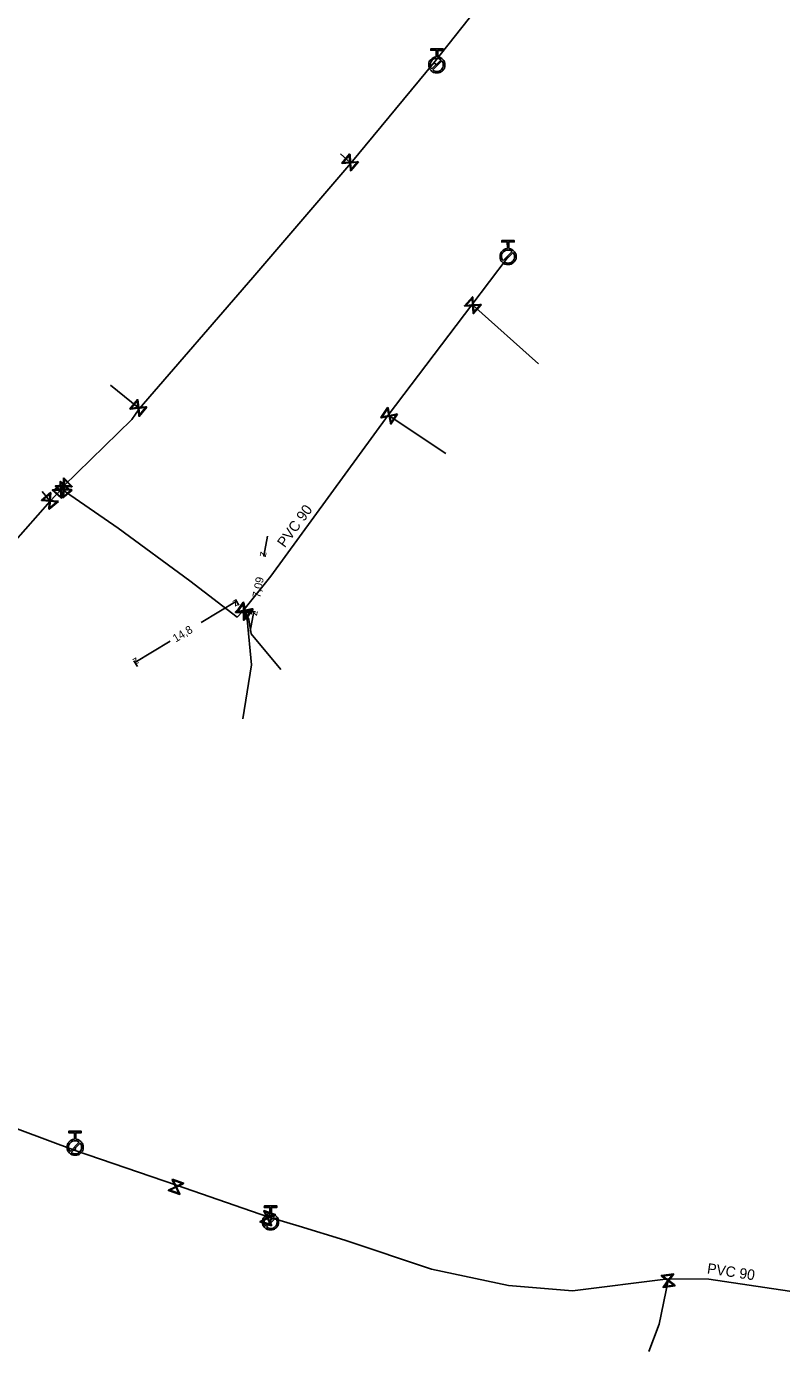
# Model space of a CAD drawing. Extents: x -641905 to -641246, y -1111750 to -1110210.
# Drawn here: x -641611.1 to -641516.8, y -1110757.5 to -1110592 of the extents above; entities that cross this region are included whole.
import ezdxf

# ---------------------------------------------------------------- set-up
doc = ezdxf.new("R2010")
doc.units = 0
for name, color, linetype in [('Default', 7, 'Continuous'), ('VP Hydrant', 7, 'Continuous'), ('VP Kótování', 7, 'Continuous'), ('VP Přípojka', 7, 'Continuous'), ('VP Řad', 7, 'Continuous'), ('VP Řad - popis', 7, 'Continuous'), ('VP Šoupě', 7, 'Continuous')]:
    doc.layers.add(name, color=color, linetype=linetype)

msp = doc.modelspace()

# ---------------------------------------------------------------- linework, layer by layer
at = {"layer": 'Default'}
for points in [[(-641559.74, -1110595.79), (-641559.39, -1110595.82), (-641559.13, -1110596.08), (-641558.84, -1110596.38), (-641558.85, -1110596.8), (-641558.86, -1110597.21), (-641559.15, -1110597.5), (-641559.45, -1110597.79), (-641559.87, -1110597.78), (-641560.28, -1110597.77), (-641560.57, -1110597.48), (-641560.86, -1110597.18), (-641560.85, -1110596.77), (-641560.84, -1110596.35), (-641560.55, -1110596.06), (-641560.29, -1110595.81), (-641559.93, -1110595.78)], [(-641559.33, -1110596.15), (-641559.55, -1110595.97), (-641559.84, -1110595.97), (-641560.18, -1110595.96), (-641560.42, -1110596.19), (-641560.66, -1110596.43), (-641560.66, -1110596.77), (-641560.67, -1110597.06), (-641560.49, -1110597.28)], [(-641560.37, -1110597.41), (-641560.15, -1110597.59), (-641559.86, -1110597.59), (-641559.53, -1110597.6), (-641559.29, -1110597.36), (-641559.04, -1110597.13), (-641559.04, -1110596.79), (-641559.04, -1110596.5), (-641559.21, -1110596.28)], [(-641550.86, -1110619.72), (-641550.5, -1110619.75), (-641550.24, -1110620.01), (-641549.95, -1110620.3), (-641549.95, -1110620.72), (-641549.95, -1110621.13), (-641550.24, -1110621.43), (-641550.53, -1110621.72), (-641550.95, -1110621.72), (-641551.36, -1110621.72), (-641551.65, -1110621.43), (-641551.95, -1110621.14), (-641551.95, -1110620.73), (-641551.95, -1110620.31), (-641551.66, -1110620.02), (-641551.4, -1110619.75), (-641551.04, -1110619.72)], [(-641550.44, -1110620.08), (-641550.66, -1110619.9), (-641550.95, -1110619.91), (-641551.29, -1110619.91), (-641551.53, -1110620.15), (-641551.77, -1110620.38), (-641551.76, -1110620.72), (-641551.76, -1110621.01), (-641551.58, -1110621.23)], [(-641551.45, -1110621.36), (-641551.24, -1110621.53), (-641550.95, -1110621.53), (-641550.61, -1110621.53), (-641550.38, -1110621.29), (-641550.14, -1110621.05), (-641550.14, -1110620.72), (-641550.14, -1110620.43), (-641550.31, -1110620.21)], [(-641604.96, -1110731), (-641604.6, -1110731.03), (-641604.34, -1110731.29), (-641604.05, -1110731.58), (-641604.05, -1110732), (-641604.05, -1110732.41), (-641604.34, -1110732.7), (-641604.63, -1110733), (-641605.05, -1110733), (-641605.46, -1110733), (-641605.75, -1110732.71), (-641606.05, -1110732.42), (-641606.05, -1110732.01), (-641606.05, -1110731.59), (-641605.76, -1110731.3), (-641605.51, -1110731.03), (-641605.15, -1110731)], [(-641604.55, -1110731.36), (-641604.76, -1110731.18), (-641605.06, -1110731.19), (-641605.39, -1110731.19), (-641605.63, -1110731.43), (-641605.87, -1110731.66), (-641605.86, -1110732), (-641605.86, -1110732.29), (-641605.68, -1110732.51)], [(-641605.55, -1110732.64), (-641605.34, -1110732.81), (-641605.05, -1110732.81), (-641604.71, -1110732.81), (-641604.48, -1110732.57), (-641604.24, -1110732.33), (-641604.24, -1110731.99), (-641604.24, -1110731.71), (-641604.42, -1110731.49)], [(-641580.53, -1110740.33), (-641580.18, -1110740.36), (-641579.92, -1110740.63), (-641579.63, -1110740.92), (-641579.63, -1110741.34), (-641579.63, -1110741.75), (-641579.93, -1110742.04), (-641580.22, -1110742.33), (-641580.64, -1110742.33), (-641581.05, -1110742.33), (-641581.34, -1110742.04), (-641581.63, -1110741.74), (-641581.63, -1110741.33), (-641581.63, -1110740.91), (-641581.34, -1110740.62), (-641581.08, -1110740.36), (-641580.72, -1110740.33)], [(-641580.12, -1110740.69), (-641580.34, -1110740.52), (-641580.63, -1110740.52), (-641580.97, -1110740.51), (-641581.21, -1110740.75), (-641581.44, -1110740.99), (-641581.44, -1110741.33), (-641581.45, -1110741.62), (-641581.27, -1110741.84)], [(-641581.14, -1110741.96), (-641580.92, -1110742.14), (-641580.63, -1110742.14), (-641580.3, -1110742.14), (-641580.06, -1110741.91), (-641579.82, -1110741.67), (-641579.82, -1110741.33), (-641579.82, -1110741.04), (-641579.99, -1110740.82)]]:
    msp.add_open_spline(points, degree=3, dxfattribs=at)
at = {"layer": 'VP Hydrant'}
for points in [[(-641559.93, -1110595.78), (-641559.92, -1110594.96), (-641560.61, -1110594.95), (-641560.6, -1110594.77), (-641559.04, -1110594.79), (-641559.04, -1110594.97), (-641559.73, -1110594.97), (-641559.74, -1110595.79)], [(-641560.49, -1110597.28), (-641559.33, -1110596.15)], [(-641559.21, -1110596.28), (-641560.37, -1110597.41)], [(-641551.04, -1110619.72), (-641551.05, -1110618.9), (-641551.74, -1110618.91), (-641551.74, -1110618.72), (-641550.18, -1110618.72), (-641550.17, -1110618.9), (-641550.86, -1110618.9), (-641550.86, -1110619.72)], [(-641551.58, -1110621.23), (-641550.44, -1110620.08)], [(-641550.31, -1110620.21), (-641551.45, -1110621.36)], [(-641605.15, -1110731), (-641605.15, -1110730.18), (-641605.84, -1110730.19), (-641605.84, -1110730), (-641604.28, -1110730), (-641604.28, -1110730.18), (-641604.97, -1110730.18), (-641604.96, -1110731)], [(-641605.68, -1110732.51), (-641604.55, -1110731.36)], [(-641604.42, -1110731.49), (-641605.55, -1110732.64)], [(-641580.72, -1110740.33), (-641580.72, -1110739.51), (-641581.41, -1110739.51), (-641581.4, -1110739.33), (-641579.84, -1110739.33), (-641579.84, -1110739.52), (-641580.53, -1110739.51), (-641580.53, -1110740.33)], [(-641581.27, -1110741.84), (-641580.12, -1110740.69)], [(-641579.99, -1110740.82), (-641581.14, -1110741.96)]]:
    msp.add_lwpolyline(points, dxfattribs=at)
at = {"layer": 'VP Kótování'}
for points in [[(-641581.02, -1110655.65), (-641581.47, -1110658.11)], [(-641581.52, -1110658.1), (-641581.22, -1110658.15)], [(-641589.31, -1110666.45), (-641584.9, -1110663.79)], [(-641584.6, -1110664.29), (-641585.03, -1110663.58)], [(-641583.19, -1110667.54), (-641582.74, -1110665.08)], [(-641582.79, -1110665.07), (-641582.5, -1110665.12)], [(-641593.16, -1110668.78), (-641597.57, -1110671.44)], [(-641597.27, -1110671.94), (-641597.7, -1110671.23)]]:
    msp.add_lwpolyline(points, dxfattribs=at)
at = {"layer": 'VP Přípojka'}
for points in [[(-641560.21, -1110596.51), (-641560.03, -1110596.65), (-641559.85, -1110596.78)], [(-641570.58, -1110609.06), (-641570.68, -1110608.97), (-641571.9, -1110607.91)], [(-641551.08, -1110620.91), (-641550.95, -1110620.72)], [(-641555.46, -1110626.76), (-641555.34, -1110626.81), (-641547.13, -1110634.11)], [(-641597.05, -1110639.76), (-641597.15, -1110639.63), (-641600.65, -1110636.79)], [(-641565.92, -1110640.54), (-641565.79, -1110640.62), (-641558.72, -1110645.33)], [(-641608.2, -1110651.25), (-641609.19, -1110650.09)], [(-641584.1, -1110678.47), (-641583.02, -1110671.73), (-641583.57, -1110666.06), (-641583.97, -1110665.12), (-641584.08, -1110665.01)], [(-641583.95, -1110664.87), (-641583.85, -1110664.94), (-641583.36, -1110666.08), (-641583.07, -1110667.84)], [(-641583.07, -1110667.84), (-641579.33, -1110672.31)], [(-641605.04, -1110732.39), (-641604.99, -1110732.24), (-641605.05, -1110732)], [(-641592.38, -1110736.75), (-641592.44, -1110736.94)], [(-641580.95, -1110740.68), (-641581, -1110740.85)], [(-641580.55, -1110740.8), (-641580.6, -1110741.04), (-641580.63, -1110741.33)], [(-641530.96, -1110748.44), (-641530.93, -1110748.65), (-641532.07, -1110754.09), (-641533.35, -1110757.51)]]:
    msp.add_lwpolyline(points, dxfattribs=at)
at = {"layer": 'VP Řad'}
for points in [[(-641606.72, -1110649.72), (-641606.63, -1110649.64), (-641606.61, -1110649.53), (-641606.49, -1110649.41), (-641597.96, -1110641.06), (-641597.05, -1110639.76), (-641582.85, -1110623.35), (-641570.58, -1110609.06), (-641560.21, -1110596.51), (-641554.97, -1110589.92), (-641538.7, -1110571.11), (-641533.56, -1110565.36), (-641525.73, -1110556.61), (-641525.22, -1110556.04), (-641523.66, -1110554.29), (-641522.92, -1110554.82), (-641518.3, -1110558.16), (-641514.31, -1110561.04), (-641510.94, -1110563.03), (-641509.87, -1110563.7)], [(-641606.63, -1110649.64), (-641606.6, -1110649.69), (-641606.49, -1110649.81), (-641606.24, -1110650.1), (-641599.67, -1110654.67), (-641590.73, -1110661.24), (-641584.82, -1110665.77), (-641584.08, -1110665.01), (-641583.95, -1110664.87), (-641580.61, -1110660.63), (-641565.92, -1110640.54), (-641555.46, -1110626.76), (-641551.08, -1110620.91)], [(-641643.86, -1110695.96), (-641643.82, -1110695.92), (-641643.71, -1110695.79), (-641639.46, -1110690.99), (-641631.18, -1110680.23), (-641624.38, -1110671.68), (-641621.52, -1110667.9), (-641614.34, -1110658.28), (-641608.15, -1110651.29), (-641606.84, -1110649.85), (-641606.72, -1110649.72)], [(-641624.02, -1110725.37), (-641622.04, -1110726.09), (-641605.04, -1110732.39), (-641592.38, -1110736.75), (-641580.95, -1110740.68), (-641580.55, -1110740.8), (-641577.05, -1110741.87), (-641571.34, -1110743.62), (-641560.51, -1110747.22), (-641550.89, -1110749.28), (-641542.88, -1110749.95), (-641530.96, -1110748.44), (-641525.88, -1110748.46), (-641513.84, -1110750.25), (-641507.42, -1110753.04), (-641507.31, -1110753.07)]]:
    msp.add_lwpolyline(points, dxfattribs=at)
at = {"layer": 'VP Šoupě'}
for points in [[(-641569.62, -1110608.9), (-641570.61, -1110610.03), (-641570.66, -1110609.99), (-641570.66, -1110609.86), (-641570.72, -1110609.02), (-641571.69, -1110609.09), (-641571.74, -1110609.04), (-641570.75, -1110607.91), (-641570.7, -1110607.96), (-641570.64, -1110608.92), (-641569.8, -1110608.87), (-641569.67, -1110608.85), (-641569.62, -1110608.9)], [(-641571.57, -1110608.99), (-641570.73, -1110608.93), (-641570.79, -1110608.09), (-641571.57, -1110608.99)], [(-641569.8, -1110608.95), (-641570.63, -1110609.01), (-641570.57, -1110609.85), (-641569.8, -1110608.95)], [(-641554.28, -1110626.75), (-641555.28, -1110627.87), (-641555.33, -1110627.83), (-641555.33, -1110627.7), (-641555.38, -1110626.86), (-641556.35, -1110626.92), (-641556.4, -1110626.87), (-641555.4, -1110625.75), (-641555.35, -1110625.8), (-641555.3, -1110626.77), (-641554.46, -1110626.71), (-641554.33, -1110626.7), (-641554.28, -1110626.75)], [(-641556.23, -1110626.82), (-641555.39, -1110626.77), (-641555.44, -1110625.93), (-641556.23, -1110626.82)], [(-641554.46, -1110626.8), (-641555.29, -1110626.85), (-641555.24, -1110627.69), (-641554.46, -1110626.8)], [(-641596.09, -1110639.52), (-641597.04, -1110640.69), (-641597.09, -1110640.64), (-641597.1, -1110640.52), (-641597.19, -1110639.68), (-641598.15, -1110639.78), (-641598.2, -1110639.74), (-641597.26, -1110638.58), (-641597.21, -1110638.62), (-641597.11, -1110639.58), (-641596.27, -1110639.5), (-641596.15, -1110639.48), (-641596.09, -1110639.52)], [(-641598.04, -1110639.68), (-641597.2, -1110639.59), (-641597.29, -1110638.76), (-641598.04, -1110639.68)], [(-641596.27, -1110639.58), (-641597.1, -1110639.67), (-641597.01, -1110640.5), (-641596.27, -1110639.58)], [(-641564.75, -1110640.41), (-641565.58, -1110641.66), (-641565.64, -1110641.62), (-641565.66, -1110641.5), (-641565.82, -1110640.67), (-641566.78, -1110640.87), (-641566.83, -1110640.83), (-641566, -1110639.58), (-641565.94, -1110639.62), (-641565.75, -1110640.57), (-641564.93, -1110640.4), (-641564.8, -1110640.38), (-641564.75, -1110640.41)], [(-641566.67, -1110640.75), (-641565.84, -1110640.59), (-641566.01, -1110639.76), (-641566.67, -1110640.75)], [(-641564.92, -1110640.49), (-641565.74, -1110640.66), (-641565.57, -1110641.48), (-641564.92, -1110640.49)], [(-641606.89, -1110648.79), (-641605.78, -1110649.8), (-641605.83, -1110649.85), (-641605.95, -1110649.85), (-641606.79, -1110649.89), (-641606.75, -1110650.86), (-641606.79, -1110650.91), (-641607.9, -1110649.9), (-641607.86, -1110649.85), (-641606.89, -1110649.81), (-641606.93, -1110648.97), (-641606.93, -1110648.84), (-641606.89, -1110648.79)], [(-641605.44, -1110649.89), (-641606.57, -1110650.87), (-641606.61, -1110650.83), (-641606.6, -1110650.7), (-641606.55, -1110649.86), (-641607.52, -1110649.8), (-641607.56, -1110649.75), (-641606.43, -1110648.76), (-641606.39, -1110648.81), (-641606.45, -1110649.78), (-641605.62, -1110649.83), (-641605.49, -1110649.84), (-641605.44, -1110649.89)], [(-641606.47, -1110648.36), (-641605.42, -1110649.43), (-641605.47, -1110649.48), (-641605.6, -1110649.47), (-641606.44, -1110649.46), (-641606.45, -1110650.43), (-641606.49, -1110650.48), (-641607.54, -1110649.41), (-641607.5, -1110649.36), (-641606.53, -1110649.37), (-641606.52, -1110648.53), (-641606.52, -1110648.4), (-641606.47, -1110648.36)], [(-641607.38, -1110649.72), (-641606.54, -1110649.77), (-641606.49, -1110648.93), (-641607.38, -1110649.72)], [(-641606.84, -1110648.97), (-641606.8, -1110649.8), (-641605.96, -1110649.76), (-641606.84, -1110648.97)], [(-641606.43, -1110648.54), (-641606.44, -1110649.37), (-641605.6, -1110649.38), (-641606.43, -1110648.54)], [(-641607.15, -1110651.32), (-641608.29, -1110652.3), (-641608.34, -1110652.25), (-641608.32, -1110652.12), (-641608.26, -1110651.28), (-641609.22, -1110651.21), (-641609.27, -1110651.16), (-641608.13, -1110650.18), (-641608.09, -1110650.23), (-641608.16, -1110651.2), (-641607.32, -1110651.27), (-641607.2, -1110651.27), (-641607.15, -1110651.32)], [(-641609.09, -1110651.13), (-641608.25, -1110651.19), (-641608.19, -1110650.36), (-641609.09, -1110651.13)], [(-641606.84, -1110650.74), (-641606.88, -1110649.9), (-641607.72, -1110649.94), (-641606.84, -1110650.74)], [(-641606.53, -1110650.3), (-641606.53, -1110649.46), (-641607.37, -1110649.45), (-641606.53, -1110650.3)], [(-641605.62, -1110649.92), (-641606.46, -1110649.86), (-641606.51, -1110650.7), (-641605.62, -1110649.92)], [(-641607.33, -1110651.35), (-641608.17, -1110651.29), (-641608.23, -1110652.12), (-641607.33, -1110651.35)], [(-641582.82, -1110664.76), (-641583.68, -1110665.99), (-641583.73, -1110665.95), (-641583.75, -1110665.83), (-641583.9, -1110665), (-641584.85, -1110665.17), (-641584.91, -1110665.13), (-641584.05, -1110663.9), (-641583.99, -1110663.94), (-641583.82, -1110664.9), (-641583, -1110664.75), (-641582.87, -1110664.73), (-641582.82, -1110664.76)], [(-641582.91, -1110665.12), (-641583.97, -1110666.18), (-641584.02, -1110666.14), (-641584.02, -1110666.01), (-641584.02, -1110665.17), (-641584.99, -1110665.17), (-641585.03, -1110665.12), (-641583.97, -1110664.06), (-641583.93, -1110664.11), (-641583.93, -1110665.08), (-641583.09, -1110665.08), (-641582.96, -1110665.07), (-641582.91, -1110665.12)], [(-641584.86, -1110665.08), (-641584.02, -1110665.08), (-641584.02, -1110664.24), (-641584.86, -1110665.08)], [(-641584.74, -1110665.06), (-641583.91, -1110664.91), (-641584.06, -1110664.08), (-641584.74, -1110665.06)], [(-641583.09, -1110665.17), (-641583.93, -1110665.17), (-641583.93, -1110666), (-641583.09, -1110665.17)], [(-641582.98, -1110664.84), (-641583.81, -1110664.98), (-641583.66, -1110665.81), (-641582.98, -1110664.84)], [(-641592.9, -1110735.98), (-641591.49, -1110736.47), (-641591.51, -1110736.53), (-641591.63, -1110736.59), (-641592.38, -1110736.96), (-641591.95, -1110737.83), (-641591.97, -1110737.89), (-641593.39, -1110737.4), (-641593.37, -1110737.34), (-641592.5, -1110736.92), (-641592.87, -1110736.16), (-641592.93, -1110736.05), (-641592.9, -1110735.98)], [(-641592.79, -1110736.12), (-641592.42, -1110736.88), (-641591.67, -1110736.51), (-641592.79, -1110736.12)], [(-641592.09, -1110737.75), (-641592.46, -1110736.99), (-641593.21, -1110737.36), (-641592.09, -1110737.75)], [(-641581.47, -1110739.9), (-641580.05, -1110740.38), (-641580.07, -1110740.45), (-641580.19, -1110740.5), (-641580.94, -1110740.87), (-641580.51, -1110741.74), (-641580.53, -1110741.8), (-641581.95, -1110741.32), (-641581.93, -1110741.25), (-641581.06, -1110740.83), (-641581.43, -1110740.07), (-641581.49, -1110739.96), (-641581.47, -1110739.9)], [(-641581.35, -1110740.04), (-641580.98, -1110740.79), (-641580.23, -1110740.42), (-641581.35, -1110740.04)], [(-641580.65, -1110741.66), (-641581.02, -1110740.91), (-641581.77, -1110741.28), (-641580.65, -1110741.66)], [(-641530.08, -1110749.29), (-641531.57, -1110749.5), (-641531.58, -1110749.43), (-641531.5, -1110749.33), (-641530.99, -1110748.66), (-641531.77, -1110748.08), (-641531.78, -1110748.01), (-641530.29, -1110747.8), (-641530.28, -1110747.87), (-641530.87, -1110748.64), (-641530.2, -1110749.15), (-641530.09, -1110749.22), (-641530.08, -1110749.29)], [(-641531.61, -1110748.08), (-641530.94, -1110748.59), (-641530.44, -1110747.92), (-641531.61, -1110748.08)], [(-641530.25, -1110749.22), (-641530.92, -1110748.71), (-641531.42, -1110749.38), (-641530.25, -1110749.22)]]:
    msp.add_lwpolyline(points, dxfattribs=at)

# ---------------------------------------------------------------- texts
at = {"layer": 'VP Kótování'}
for s, rotation, p in [('z', 259.6182, (-641581.87, -1110657.53)), ('7,09', 79.6182, (-641581.93, -1110663.41)), ('z', 31.1432, (-641585.07, -1110664.48)), ('z', 79.6182, (-641582.34, -1110665.66)), ('14,8', 31.1432, (-641592.48, -1110668.95)), ('z', 211.1432, (-641597.4, -1110670.76))]:
    msp.add_text(s, height=1, rotation=rotation, dxfattribs=at).set_placement(p)
at = {"layer": 'VP Řad - popis'}
for rotation, p in [(53.8254, (-641578.86, -1110657.17)), (351.5437, (-641526.14, -1110747.74))]:
    msp.add_text('PVC 90', height=1.3, rotation=rotation, dxfattribs=at).set_placement(p)

doc.saveas('drawing.dxf')
